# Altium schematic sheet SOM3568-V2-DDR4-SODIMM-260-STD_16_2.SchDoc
size 594 x 420 mm
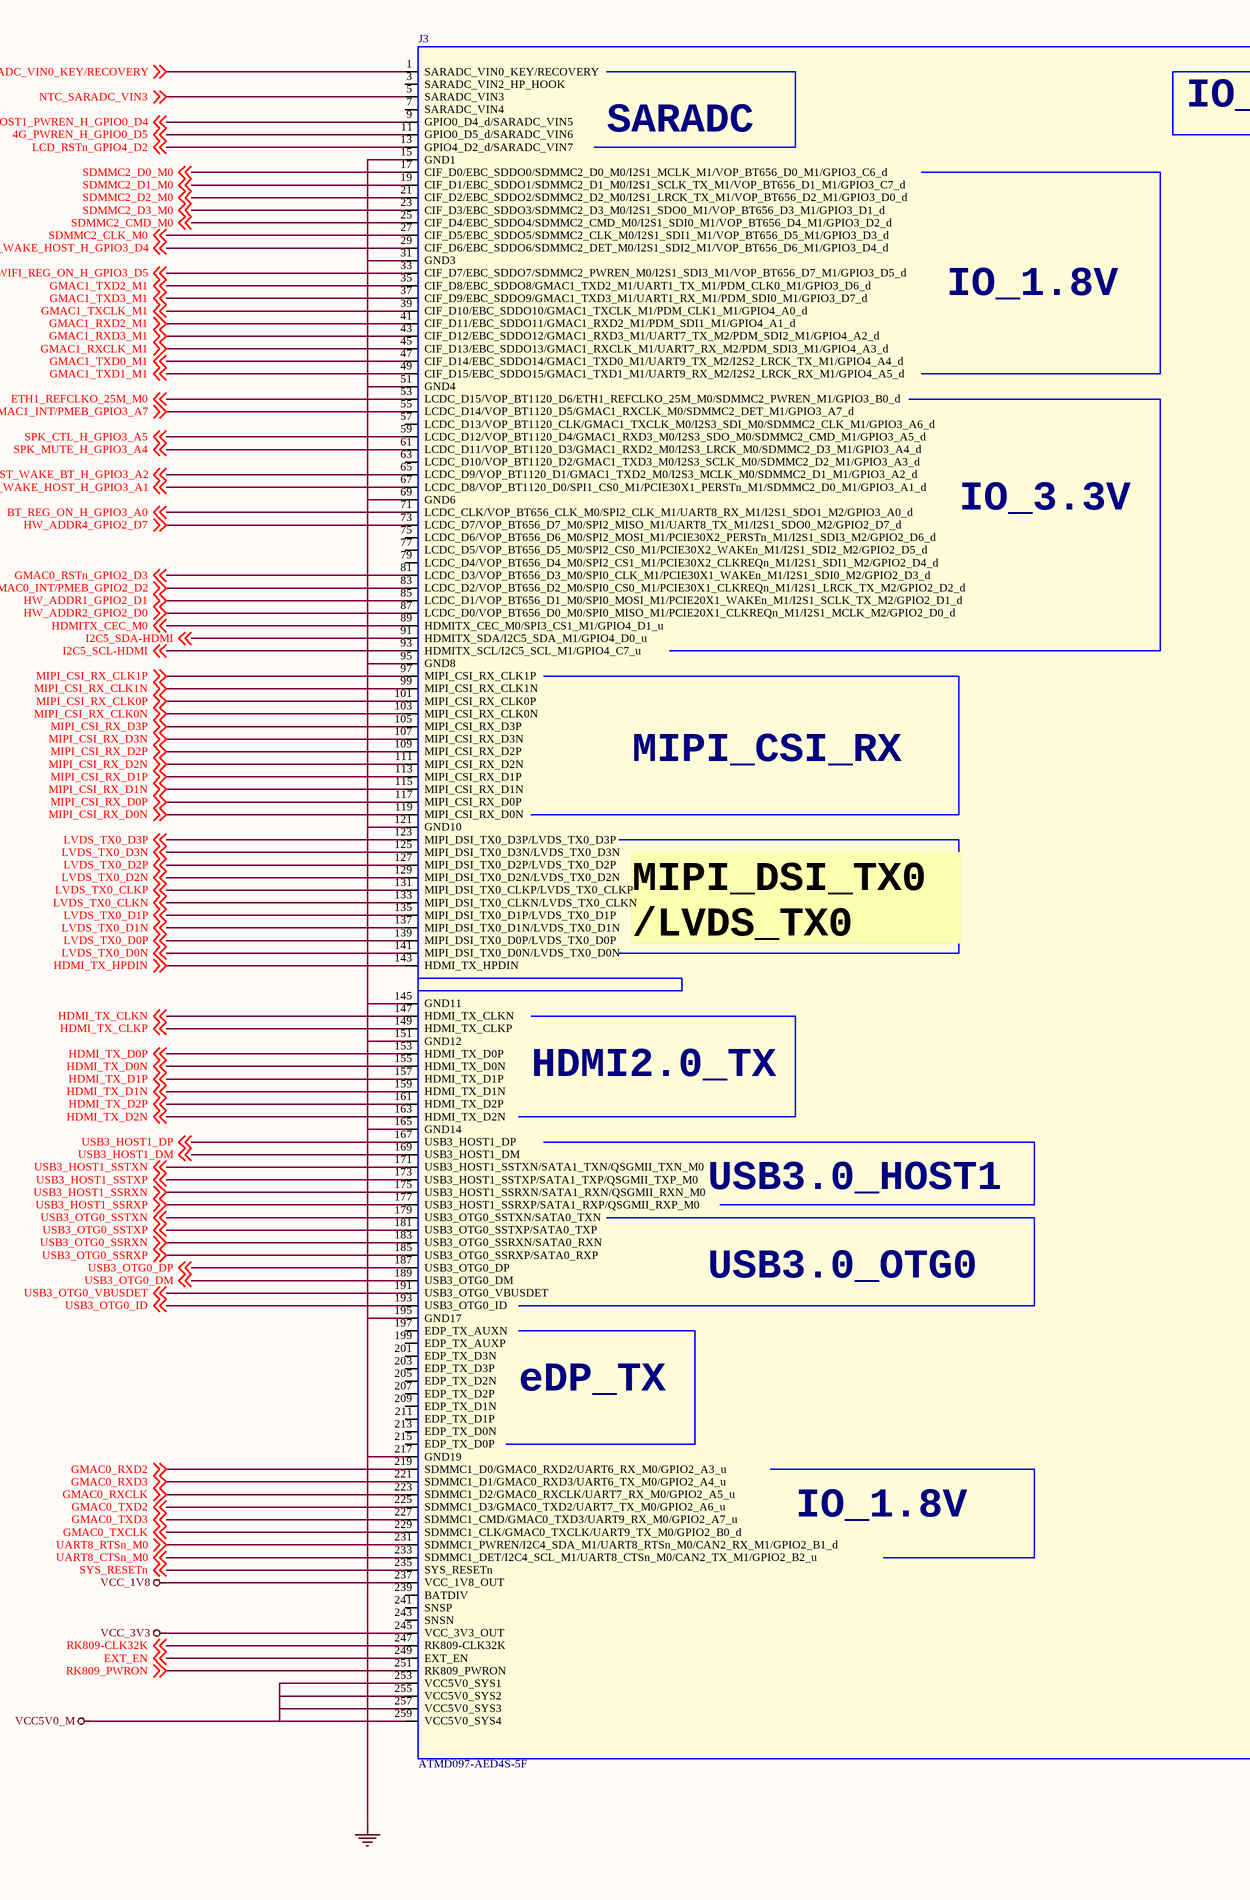
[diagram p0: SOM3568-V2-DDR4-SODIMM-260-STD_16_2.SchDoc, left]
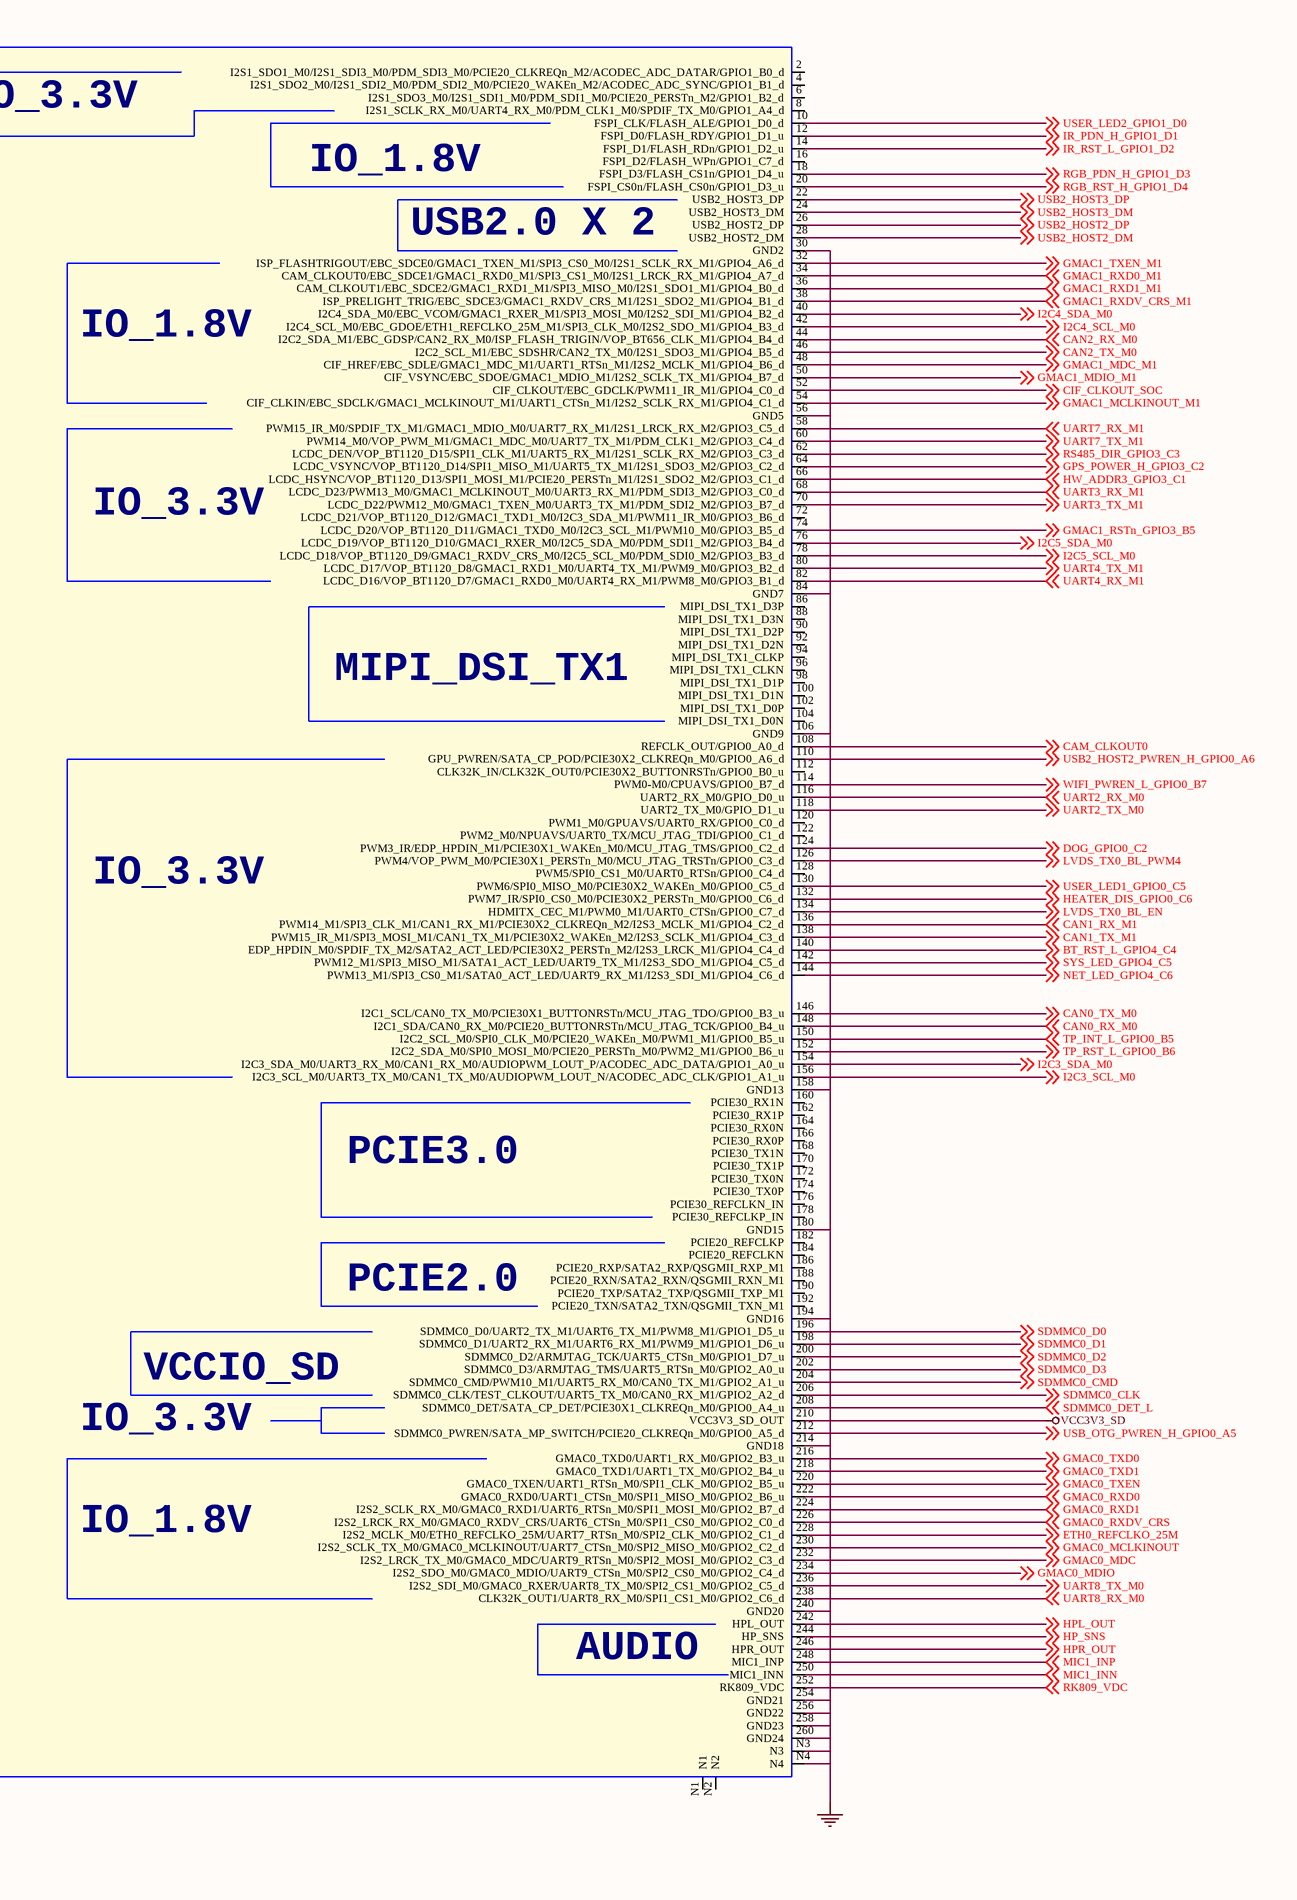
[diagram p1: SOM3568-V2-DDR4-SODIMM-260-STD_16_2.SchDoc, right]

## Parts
J3  ATMD097-AED4S-5F  [DDR4-SODIMM-260P-STD]

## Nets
GND: J3.15(GND1) J3.30(GND2) J3.31(GND3) J3.51(GND4) J3.56(GND5) J3.69(GND6) J3.84(GND7) J3.95(GND8) J3.106(GND9) J3.121(GND10) J3.145(GND11) J3.151(GND12) J3.158(GND13) J3.165(GND14) J3.180(GND15) J3.194(GND16) J3.195(GND17) J3.214(GND18) J3.217(GND19) J3.240(GND20) J3.254(GND21) J3.256(GND22) J3.258(GND23) J3.260(GND24) J3.N3 J3.N4
VCC3V3_SD: J3.210(VCC3V3_SD_OUT)
VCC5V0_M: J3.253(VCC5V0_SYS1) J3.255(VCC5V0_SYS2) J3.257(VCC5V0_SYS3) J3.259(VCC5V0_SYS4)
VCC_1V8: J3.237(VCC_1V8_OUT)
VCC_3V3: J3.245(VCC_3V3_OUT)
4G_PWREN_H_GPIO0_D5: J3.11(GPIO0_D5_d/SARADC_VIN6) ; off-sheet 4G_PWREN_H_GPIO0_D5
BT_REG_ON_H_GPIO3_A0: J3.71(LCDC_CLK/VOP_BT656_CLK_M0/SPI2_CLK_M1/UART8_RX_M1/I2S1_SDO1_M2/GPIO3_A0_d) ; off-sheet BT_REG_ON_H_GPIO3_A0
BT_RST_L_GPIO4_C4: J3.140(EDP_HPDIN_M0/SPDIF_TX_M2/SATA2_ACT_LED/PCIE30X2_PERSTn_M2/I2S3_LRCK_M1/GPIO4_C4_d) ; off-sheet BT_RST_L_GPIO4_C4
BT_WAKE_HOST_H_GPIO3_A1: J3.67(LCDC_D8/VOP_BT1120_D0/SPI1_CS0_M1/PCIE30X1_PERSTn_M1/SDMMC2_D0_M1/GPIO3_A1_d) ; off-sheet BT_WAKE_HOST_H_GPIO3_A1
CAM_CLKOUT0: J3.108(REFCLK_OUT/GPIO0_A0_d) ; off-sheet CAM_CLKOUT0
CAN0_RX_M0: J3.148(I2C1_SDA/CAN0_RX_M0/PCIE20_BUTTONRSTn/MCU_JTAG_TCK/GPIO0_B4_u) ; off-sheet CAN0_RX_M0
CAN0_TX_M0: J3.146(I2C1_SCL/CAN0_TX_M0/PCIE30X1_BUTTONRSTn/MCU_JTAG_TDO/GPIO0_B3_u) ; off-sheet CAN0_TX_M0
CAN1_RX_M1: J3.136(PWM14_M1/SPI3_CLK_M1/CAN1_RX_M1/PCIE30X2_CLKREQn_M2/I2S3_MCLK_M1/GPIO4_C2_d) ; off-sheet CAN1_RX_M1
CAN1_TX_M1: J3.138(PWM15_IR_M1/SPI3_MOSI_M1/CAN1_TX_M1/PCIE30X2_WAKEn_M2/I2S3_SCLK_M1/GPIO4_C3_d) ; off-sheet CAN1_TX_M1
CAN2_RX_M0: J3.44(I2C2_SDA_M1/EBC_GDSP/CAN2_RX_M0/ISP_FLASH_TRIGIN/VOP_BT656_CLK_M1/GPIO4_B4_d) ; off-sheet CAN2_RX_M0
CAN2_TX_M0: J3.46(I2C2_SCL_M1/EBC_SDSHR/CAN2_TX_M0/I2S1_SDO3_M1/GPIO4_B5_d) ; off-sheet CAN2_TX_M0
CIF_CLKOUT_SOC: J3.52(CIF_CLKOUT/EBC_GDCLK/PWM11_IR_M1/GPIO4_C0_d) ; off-sheet CIF_CLKOUT_SOC
DOG_GPIO0_C2: J3.124(PWM3_IR/EDP_HPDIN_M1/PCIE30X1_WAKEn_M0/MCU_JTAG_TMS/GPIO0_C2_d) ; off-sheet DOG_GPIO0_C2
ETH0_REFCLKO_25M: J3.228(I2S2_MCLK_M0/ETH0_REFCLKO_25M/UART7_RTSn_M0/SPI2_CLK_M0/GPIO2_C1_d) ; off-sheet ETH0_REFCLKO_25M
ETH1_REFCLKO_25M_M0: J3.53(LCDC_D15/VOP_BT1120_D6/ETH1_REFCLKO_25M_M0/SDMMC2_PWREN_M1/GPIO3_B0_d) ; off-sheet ETH1_REFCLKO_25M_M0
EXT_EN: J3.249(EXT_EN) ; off-sheet EXT_EN
GMAC0_INT/PMEB_GPIO2_D2: J3.83(LCDC_D2/VOP_BT656_D2_M0/SPI0_CS0_M1/PCIE30X1_CLKREQn_M1/I2S1_LRCK_TX_M2/GPIO2_D2_d) ; off-sheet GMAC0_INT/PMEB_GPIO2_D2
GMAC0_MCLKINOUT: J3.230(I2S2_SCLK_TX_M0/GMAC0_MCLKINOUT/UART7_CTSn_M0/SPI2_MISO_M0/GPIO2_C2_d) ; off-sheet GMAC0_MCLKINOUT
GMAC0_MDC: J3.232(I2S2_LRCK_TX_M0/GMAC0_MDC/UART9_RTSn_M0/SPI2_MOSI_M0/GPIO2_C3_d) ; off-sheet GMAC0_MDC
GMAC0_MDIO: J3.234(I2S2_SDO_M0/GMAC0_MDIO/UART9_CTSn_M0/SPI2_CS0_M0/GPIO2_C4_d) ; off-sheet GMAC0_MDIO
GMAC0_RSTn_GPIO2_D3: J3.81(LCDC_D3/VOP_BT656_D3_M0/SPI0_CLK_M1/PCIE30X1_WAKEn_M1/I2S1_SDI0_M2/GPIO2_D3_d) ; off-sheet GMAC0_RSTn_GPIO2_D3
GMAC0_RXCLK: J3.223(SDMMC1_D2/GMAC0_RXCLK/UART7_RX_M0/GPIO2_A5_u) ; off-sheet GMAC0_RXCLK
GMAC0_RXD0: J3.222(GMAC0_RXD0/UART1_CTSn_M0/SPI1_MISO_M0/GPIO2_B6_u) ; off-sheet GMAC0_RXD0
GMAC0_RXD1: J3.224(I2S2_SCLK_RX_M0/GMAC0_RXD1/UART6_RTSn_M0/SPI1_MOSI_M0/GPIO2_B7_d) ; off-sheet GMAC0_RXD1
GMAC0_RXD2: J3.219(SDMMC1_D0/GMAC0_RXD2/UART6_RX_M0/GPIO2_A3_u) ; off-sheet GMAC0_RXD2
GMAC0_RXD3: J3.221(SDMMC1_D1/GMAC0_RXD3/UART6_TX_M0/GPIO2_A4_u) ; off-sheet GMAC0_RXD3
GMAC0_RXDV_CRS: J3.226(I2S2_LRCK_RX_M0/GMAC0_RXDV_CRS/UART6_CTSn_M0/SPI1_CS0_M0/GPIO2_C0_d) ; off-sheet GMAC0_RXDV_CRS
GMAC0_TXCLK: J3.229(SDMMC1_CLK/GMAC0_TXCLK/UART9_TX_M0/GPIO2_B0_d) ; off-sheet GMAC0_TXCLK
GMAC0_TXD0: J3.216(GMAC0_TXD0/UART1_RX_M0/GPIO2_B3_u) ; off-sheet GMAC0_TXD0
GMAC0_TXD1: J3.218(GMAC0_TXD1/UART1_TX_M0/GPIO2_B4_u) ; off-sheet GMAC0_TXD1
GMAC0_TXD2: J3.225(SDMMC1_D3/GMAC0_TXD2/UART7_TX_M0/GPIO2_A6_u) ; off-sheet GMAC0_TXD2
GMAC0_TXD3: J3.227(SDMMC1_CMD/GMAC0_TXD3/UART9_RX_M0/GPIO2_A7_u) ; off-sheet GMAC0_TXD3
GMAC0_TXEN: J3.220(GMAC0_TXEN/UART1_RTSn_M0/SPI1_CLK_M0/GPIO2_B5_u) ; off-sheet GMAC0_TXEN
GMAC1_INT/PMEB_GPIO3_A7: J3.55(LCDC_D14/VOP_BT1120_D5/GMAC1_RXCLK_M0/SDMMC2_DET_M1/GPIO3_A7_d) ; off-sheet GMAC1_INT/PMEB_GPIO3_A7
GMAC1_MCLKINOUT_M1: J3.54(CIF_CLKIN/EBC_SDCLK/GMAC1_MCLKINOUT_M1/UART1_CTSn_M1/I2S2_SCLK_RX_M1/GPIO4_C1_d) ; off-sheet GMAC1_MCLKINOUT_M1
GMAC1_MDC_M1: J3.48(CIF_HREF/EBC_SDLE/GMAC1_MDC_M1/UART1_RTSn_M1/I2S2_MCLK_M1/GPIO4_B6_d) ; off-sheet GMAC1_MDC_M1
GMAC1_MDIO_M1: J3.50(CIF_VSYNC/EBC_SDOE/GMAC1_MDIO_M1/I2S2_SCLK_TX_M1/GPIO4_B7_d) ; off-sheet GMAC1_MDIO_M1
GMAC1_RSTn_GPIO3_B5: J3.74(LCDC_D20/VOP_BT1120_D11/GMAC1_TXD0_M0/I2C3_SCL_M1/PWM10_M0/GPIO3_B5_d) ; off-sheet GMAC1_RSTn_GPIO3_B5
GMAC1_RXCLK_M1: J3.45(CIF_D13/EBC_SDDO13/GMAC1_RXCLK_M1/UART7_RX_M2/PDM_SDI3_M1/GPIO4_A3_d) ; off-sheet GMAC1_RXCLK_M1
GMAC1_RXD0_M1: J3.34(CAM_CLKOUT0/EBC_SDCE1/GMAC1_RXD0_M1/SPI3_CS1_M0/I2S1_LRCK_RX_M1/GPIO4_A7_d) ; off-sheet GMAC1_RXD0_M1
GMAC1_RXD1_M1: J3.36(CAM_CLKOUT1/EBC_SDCE2/GMAC1_RXD1_M1/SPI3_MISO_M0/I2S1_SDO1_M1/GPIO4_B0_d) ; off-sheet GMAC1_RXD1_M1
GMAC1_RXD2_M1: J3.41(CIF_D11/EBC_SDDO11/GMAC1_RXD2_M1/PDM_SDI1_M1/GPIO4_A1_d) ; off-sheet GMAC1_RXD2_M1
GMAC1_RXD3_M1: J3.43(CIF_D12/EBC_SDDO12/GMAC1_RXD3_M1/UART7_TX_M2/PDM_SDI2_M1/GPIO4_A2_d) ; off-sheet GMAC1_RXD3_M1
GMAC1_RXDV_CRS_M1: J3.38(ISP_PRELIGHT_TRIG/EBC_SDCE3/GMAC1_RXDV_CRS_M1/I2S1_SDO2_M1/GPIO4_B1_d) ; off-sheet GMAC1_RXDV_CRS_M1
GMAC1_TXCLK_M1: J3.39(CIF_D10/EBC_SDDO10/GMAC1_TXCLK_M1/PDM_CLK1_M1/GPIO4_A0_d) ; off-sheet GMAC1_TXCLK_M1
GMAC1_TXD0_M1: J3.47(CIF_D14/EBC_SDDO14/GMAC1_TXD0_M1/UART9_TX_M2/I2S2_LRCK_TX_M1/GPIO4_A4_d) ; off-sheet GMAC1_TXD0_M1
GMAC1_TXD1_M1: J3.49(CIF_D15/EBC_SDDO15/GMAC1_TXD1_M1/UART9_RX_M2/I2S2_LRCK_RX_M1/GPIO4_A5_d) ; off-sheet GMAC1_TXD1_M1
GMAC1_TXD2_M1: J3.35(CIF_D8/EBC_SDDO8/GMAC1_TXD2_M1/UART1_TX_M1/PDM_CLK0_M1/GPIO3_D6_d) ; off-sheet GMAC1_TXD2_M1
GMAC1_TXD3_M1: J3.37(CIF_D9/EBC_SDDO9/GMAC1_TXD3_M1/UART1_RX_M1/PDM_SDI0_M1/GPIO3_D7_d) ; off-sheet GMAC1_TXD3_M1
GMAC1_TXEN_M1: J3.32(ISP_FLASHTRIGOUT/EBC_SDCE0/GMAC1_TXEN_M1/SPI3_CS0_M0/I2S1_SCLK_RX_M1/GPIO4_A6_d) ; off-sheet GMAC1_TXEN_M1
GPS_POWER_H_GPIO3_C2: J3.64(LCDC_VSYNC/VOP_BT1120_D14/SPI1_MISO_M1/UART5_TX_M1/I2S1_SDO3_M2/GPIO3_C2_d) ; off-sheet GPS_POWER_H_GPIO3_C2
HDMI_TX_CLKN: J3.147(HDMI_TX_CLKN) ; off-sheet HDMI_TX_CLKN
HDMI_TX_CLKP: J3.149(HDMI_TX_CLKP) ; off-sheet HDMI_TX_CLKP
HDMI_TX_D0N: J3.155(HDMI_TX_D0N) ; off-sheet HDMI_TX_D0N
HDMI_TX_D0P: J3.153(HDMI_TX_D0P) ; off-sheet HDMI_TX_D0P
HDMI_TX_D1N: J3.159(HDMI_TX_D1N) ; off-sheet HDMI_TX_D1N
HDMI_TX_D1P: J3.157(HDMI_TX_D1P) ; off-sheet HDMI_TX_D1P
HDMI_TX_D2N: J3.163(HDMI_TX_D2N) ; off-sheet HDMI_TX_D2N
HDMI_TX_D2P: J3.161(HDMI_TX_D2P) ; off-sheet HDMI_TX_D2P
HDMI_TX_HPDIN: J3.143(HDMI_TX_HPDIN) ; off-sheet HDMI_TX_HPDIN
HDMITX_CEC_M0: J3.89(HDMITX_CEC_M0/SPI3_CS1_M1/GPIO4_D1_u) ; off-sheet HDMITX_CEC_M0
HEATER_DIS_GPIO0_C6: J3.132(PWM7_IR/SPI0_CS0_M0/PCIE30X2_PERSTn_M0/GPIO0_C6_d) ; off-sheet HEATER_DIS_GPIO0_C6
HOST_WAKE_BT_H_GPIO3_A2: J3.65(LCDC_D9/VOP_BT1120_D1/GMAC1_TXD2_M0/I2S3_MCLK_M0/SDMMC2_D1_M1/GPIO3_A2_d) ; off-sheet HOST_WAKE_BT_H_GPIO3_A2
HP_SNS: J3.244(HP_SNS) ; off-sheet HP_SNS
HPL_OUT: J3.242(HPL_OUT) ; off-sheet HPL_OUT
HPR_OUT: J3.246(HPR_OUT) ; off-sheet HPR_OUT
HW_ADDR1_GPIO2_D1: J3.85(LCDC_D1/VOP_BT656_D1_M0/SPI0_MOSI_M1/PCIE20X1_WAKEn_M1/I2S1_SCLK_TX_M2/GPIO2_D1_d) ; off-sheet HW_ADDR1_GPIO2_D1
HW_ADDR2_GPIO2_D0: J3.87(LCDC_D0/VOP_BT656_D0_M0/SPI0_MISO_M1/PCIE20X1_CLKREQn_M1/I2S1_MCLK_M2/GPIO2_D0_d) ; off-sheet HW_ADDR2_GPIO2_D0
HW_ADDR3_GPIO3_C1: J3.66(LCDC_HSYNC/VOP_BT1120_D13/SPI1_MOSI_M1/PCIE20_PERSTn_M1/I2S1_SDO2_M2/GPIO3_C1_d) ; off-sheet HW_ADDR3_GPIO3_C1
HW_ADDR4_GPIO2_D7: J3.73(LCDC_D7/VOP_BT656_D7_M0/SPI2_MISO_M1/UART8_TX_M1/I2S1_SDO0_M2/GPIO2_D7_d) ; off-sheet HW_ADDR4_GPIO2_D7
I2C3_SCL_M0: J3.156(I2C3_SCL_M0/UART3_TX_M0/CAN1_TX_M0/AUDIOPWM_LOUT_N/ACODEC_ADC_CLK/GPIO1_A1_u) ; off-sheet I2C3_SCL_M0
I2C3_SDA_M0: J3.154(I2C3_SDA_M0/UART3_RX_M0/CAN1_RX_M0/AUDIOPWM_LOUT_P/ACODEC_ADC_DATA/GPIO1_A0_u) ; off-sheet I2C3_SDA_M0
I2C4_SCL_M0: J3.42(I2C4_SCL_M0/EBC_GDOE/ETH1_REFCLKO_25M_M1/SPI3_CLK_M0/I2S2_SDO_M1/GPIO4_B3_d) ; off-sheet I2C4_SCL_M0
I2C4_SDA_M0: J3.40(I2C4_SDA_M0/EBC_VCOM/GMAC1_RXER_M1/SPI3_MOSI_M0/I2S2_SDI_M1/GPIO4_B2_d) ; off-sheet I2C4_SDA_M0
I2C5_SCL-HDMI: J3.93(HDMITX_SCL/I2C5_SCL_M1/GPIO4_C7_u) ; off-sheet I2C5_SCL-HDMI
I2C5_SCL_M0: J3.78(LCDC_D18/VOP_BT1120_D9/GMAC1_RXDV_CRS_M0/I2C5_SCL_M0/PDM_SDI0_M2/GPIO3_B3_d) ; off-sheet I2C5_SCL_M0
I2C5_SDA-HDMI: J3.91(HDMITX_SDA/I2C5_SDA_M1/GPIO4_D0_u) ; off-sheet I2C5_SDA-HDMI
I2C5_SDA_M0: J3.76(LCDC_D19/VOP_BT1120_D10/GMAC1_RXER_M0/I2C5_SDA_M0/PDM_SDI1_M2/GPIO3_B4_d) ; off-sheet I2C5_SDA_M0
IR_PDN_H_GPIO1_D1: J3.12(FSPI_D0/FLASH_RDY/GPIO1_D1_u) ; off-sheet IR_PDN_H_GPIO1_D1
IR_RST_L_GPIO1_D2: J3.14(FSPI_D1/FLASH_RDn/GPIO1_D2_u) ; off-sheet IR_RST_L_GPIO1_D2
LCD_RSTn_GPIO4_D2: J3.13(GPIO4_D2_d/SARADC_VIN7) ; off-sheet LCD_RSTn_GPIO4_D2
LVDS_TX0_BL_EN: J3.134(HDMITX_CEC_M1/PWM0_M1/UART0_CTSn/GPIO0_C7_d) ; off-sheet LVDS_TX0_BL_EN
LVDS_TX0_BL_PWM4: J3.126(PWM4/VOP_PWM_M0/PCIE30X1_PERSTn_M0/MCU_JTAG_TRSTn/GPIO0_C3_d) ; off-sheet LVDS_TX0_BL_PWM4
LVDS_TX0_CLKN: J3.133(MIPI_DSI_TX0_CLKN/LVDS_TX0_CLKN) ; off-sheet LVDS_TX0_CLKN
LVDS_TX0_CLKP: J3.131(MIPI_DSI_TX0_CLKP/LVDS_TX0_CLKP) ; off-sheet LVDS_TX0_CLKP
LVDS_TX0_D0N: J3.141(MIPI_DSI_TX0_D0N/LVDS_TX0_D0N) ; off-sheet LVDS_TX0_D0N
LVDS_TX0_D0P: J3.139(MIPI_DSI_TX0_D0P/LVDS_TX0_D0P) ; off-sheet LVDS_TX0_D0P
LVDS_TX0_D1N: J3.137(MIPI_DSI_TX0_D1N/LVDS_TX0_D1N) ; off-sheet LVDS_TX0_D1N
LVDS_TX0_D1P: J3.135(MIPI_DSI_TX0_D1P/LVDS_TX0_D1P) ; off-sheet LVDS_TX0_D1P
LVDS_TX0_D2N: J3.129(MIPI_DSI_TX0_D2N/LVDS_TX0_D2N) ; off-sheet LVDS_TX0_D2N
LVDS_TX0_D2P: J3.127(MIPI_DSI_TX0_D2P/LVDS_TX0_D2P) ; off-sheet LVDS_TX0_D2P
LVDS_TX0_D3N: J3.125(MIPI_DSI_TX0_D3N/LVDS_TX0_D3N) ; off-sheet LVDS_TX0_D3N
LVDS_TX0_D3P: J3.123(MIPI_DSI_TX0_D3P/LVDS_TX0_D3P) ; off-sheet LVDS_TX0_D3P
MIC1_INN: J3.250(MIC1_INN) ; off-sheet MIC1_INN
MIC1_INP: J3.248(MIC1_INP) ; off-sheet MIC1_INP
MIPI_CSI_RX_CLK0N: J3.103(MIPI_CSI_RX_CLK0N) ; off-sheet MIPI_CSI_RX_CLK0N
MIPI_CSI_RX_CLK0P: J3.101(MIPI_CSI_RX_CLK0P) ; off-sheet MIPI_CSI_RX_CLK0P
MIPI_CSI_RX_CLK1N: J3.99(MIPI_CSI_RX_CLK1N) ; off-sheet MIPI_CSI_RX_CLK1N
MIPI_CSI_RX_CLK1P: J3.97(MIPI_CSI_RX_CLK1P) ; off-sheet MIPI_CSI_RX_CLK1P
MIPI_CSI_RX_D0N: J3.119(MIPI_CSI_RX_D0N) ; off-sheet MIPI_CSI_RX_D0N
MIPI_CSI_RX_D0P: J3.117(MIPI_CSI_RX_D0P) ; off-sheet MIPI_CSI_RX_D0P
MIPI_CSI_RX_D1N: J3.115(MIPI_CSI_RX_D1N) ; off-sheet MIPI_CSI_RX_D1N
MIPI_CSI_RX_D1P: J3.113(MIPI_CSI_RX_D1P) ; off-sheet MIPI_CSI_RX_D1P
MIPI_CSI_RX_D2N: J3.111(MIPI_CSI_RX_D2N) ; off-sheet MIPI_CSI_RX_D2N
MIPI_CSI_RX_D2P: J3.109(MIPI_CSI_RX_D2P) ; off-sheet MIPI_CSI_RX_D2P
MIPI_CSI_RX_D3N: J3.107(MIPI_CSI_RX_D3N) ; off-sheet MIPI_CSI_RX_D3N
MIPI_CSI_RX_D3P: J3.105(MIPI_CSI_RX_D3P) ; off-sheet MIPI_CSI_RX_D3P
NET_LED_GPIO4_C6: J3.144(PWM13_M1/SPI3_CS0_M1/SATA0_ACT_LED/UART9_RX_M1/I2S3_SDI_M1/GPIO4_C6_d) ; off-sheet NET_LED_GPIO4_C6
NTC_SARADC_VIN3: J3.5(SARADC_VIN3) ; off-sheet NTC_SARADC_VIN3
RGB_PDN_H_GPIO1_D3: J3.18(FSPI_D3/FLASH_CS1n/GPIO1_D4_u) ; off-sheet RGB_PDN_H_GPIO1_D3
RGB_RST_H_GPIO1_D4: J3.20(FSPI_CS0n/FLASH_CS0n/GPIO1_D3_u) ; off-sheet RGB_RST_H_GPIO1_D4
RK809-CLK32K: J3.247(RK809-CLK32K) ; off-sheet RK809-CLK32K
RK809_PWRON: J3.251(RK809_PWRON) ; off-sheet RK809_PWRON
RK809_VDC: J3.252(RK809_VDC) ; off-sheet RK809_VDC
RS485_DIR_GPIO3_C3: J3.62(LCDC_DEN/VOP_BT1120_D15/SPI1_CLK_M1/UART5_RX_M1/I2S1_SCLK_RX_M2/GPIO3_C3_d) ; off-sheet RS485_DIR_GPIO3_C3
SARADC_VIN0_KEY/RECOVERY: J3.1(SARADC_VIN0_KEY/RECOVERY) ; off-sheet SARADC_VIN0_KEY/RECOVERY
SDMMC0_CLK: J3.206(SDMMC0_CLK/TEST_CLKOUT/UART5_TX_M0/CAN0_RX_M1/GPIO2_A2_d) ; off-sheet SDMMC0_CLK
SDMMC0_CMD: J3.204(SDMMC0_CMD/PWM10_M1/UART5_RX_M0/CAN0_TX_M1/GPIO2_A1_u) ; off-sheet SDMMC0_CMD
SDMMC0_D0: J3.196(SDMMC0_D0/UART2_TX_M1/UART6_TX_M1/PWM8_M1/GPIO1_D5_u) ; off-sheet SDMMC0_D0
SDMMC0_D1: J3.198(SDMMC0_D1/UART2_RX_M1/UART6_RX_M1/PWM9_M1/GPIO1_D6_u) ; off-sheet SDMMC0_D1
SDMMC0_D2: J3.200(SDMMC0_D2/ARMJTAG_TCK/UART5_CTSn_M0/GPIO1_D7_u) ; off-sheet SDMMC0_D2
SDMMC0_D3: J3.202(SDMMC0_D3/ARMJTAG_TMS/UART5_RTSn_M0/GPIO2_A0_u) ; off-sheet SDMMC0_D3
SDMMC0_DET_L: J3.208(SDMMC0_DET/SATA_CP_DET/PCIE30X1_CLKREQn_M0/GPIO0_A4_u) ; off-sheet SDMMC0_DET_L
SDMMC2_CLK_M0: J3.27(CIF_D5/EBC_SDDO5/SDMMC2_CLK_M0/I2S1_SDI1_M1/VOP_BT656_D5_M1/GPIO3_D3_d) ; off-sheet SDMMC2_CLK_M0
SDMMC2_CMD_M0: J3.25(CIF_D4/EBC_SDDO4/SDMMC2_CMD_M0/I2S1_SDI0_M1/VOP_BT656_D4_M1/GPIO3_D2_d) ; off-sheet SDMMC2_CMD_M0
SDMMC2_D0_M0: J3.17(CIF_D0/EBC_SDDO0/SDMMC2_D0_M0/I2S1_MCLK_M1/VOP_BT656_D0_M1/GPIO3_C6_d) ; off-sheet SDMMC2_D0_M0
SDMMC2_D1_M0: J3.19(CIF_D1/EBC_SDDO1/SDMMC2_D1_M0/I2S1_SCLK_TX_M1/VOP_BT656_D1_M1/GPIO3_C7_d) ; off-sheet SDMMC2_D1_M0
SDMMC2_D2_M0: J3.21(CIF_D2/EBC_SDDO2/SDMMC2_D2_M0/I2S1_LRCK_TX_M1/VOP_BT656_D2_M1/GPIO3_D0_d) ; off-sheet SDMMC2_D2_M0
SDMMC2_D3_M0: J3.23(CIF_D3/EBC_SDDO3/SDMMC2_D3_M0/I2S1_SDO0_M1/VOP_BT656_D3_M1/GPIO3_D1_d) ; off-sheet SDMMC2_D3_M0
SPK_CTL_H_GPIO3_A5: J3.59(LCDC_D12/VOP_BT1120_D4/GMAC1_RXD3_M0/I2S3_SDO_M0/SDMMC2_CMD_M1/GPIO3_A5_d) ; off-sheet SPK_CTL_H_GPIO3_A5
SPK_MUTE_H_GPIO3_A4: J3.61(LCDC_D11/VOP_BT1120_D3/GMAC1_RXD2_M0/I2S3_LRCK_M0/SDMMC2_D3_M1/GPIO3_A4_d) ; off-sheet SPK_MUTE_H_GPIO3_A4
SYS_LED_GPIO4_C5: J3.142(PWM12_M1/SPI3_MISO_M1/SATA1_ACT_LED/UART9_TX_M1/I2S3_SDO_M1/GPIO4_C5_d) ; off-sheet SYS_LED_GPIO4_C5
SYS_RESETn: J3.235(SYS_RESETn) ; off-sheet SYS_RESETn
TP_INT_L_GPIO0_B5: J3.150(I2C2_SCL_M0/SPI0_CLK_M0/PCIE20_WAKEn_M0/PWM1_M1/GPIO0_B5_u) ; off-sheet TP_INT_L_GPIO0_B5
TP_RST_L_GPIO0_B6: J3.152(I2C2_SDA_M0/SPI0_MOSI_M0/PCIE20_PERSTn_M0/PWM2_M1/GPIO0_B6_u) ; off-sheet TP_RST_L_GPIO0_B6
UART2_RX_M0: J3.116(UART2_RX_M0/GPIO_D0_u) ; off-sheet UART2_RX_M0
UART2_TX_M0: J3.118(UART2_TX_M0/GPIO_D1_u) ; off-sheet UART2_TX_M0
UART3_RX_M1: J3.68(LCDC_D23/PWM13_M0/GMAC1_MCLKINOUT_M0/UART3_RX_M1/PDM_SDI3_M2/GPIO3_C0_d) ; off-sheet UART3_RX_M1
UART3_TX_M1: J3.70(LCDC_D22/PWM12_M0/GMAC1_TXEN_M0/UART3_TX_M1/PDM_SDI2_M2/GPIO3_B7_d) ; off-sheet UART3_TX_M1
UART4_RX_M1: J3.82(LCDC_D16/VOP_BT1120_D7/GMAC1_RXD0_M0/UART4_RX_M1/PWM8_M0/GPIO3_B1_d) ; off-sheet UART4_RX_M1
UART4_TX_M1: J3.80(LCDC_D17/VOP_BT1120_D8/GMAC1_RXD1_M0/UART4_TX_M1/PWM9_M0/GPIO3_B2_d) ; off-sheet UART4_TX_M1
UART7_RX_M1: J3.58(PWM15_IR_M0/SPDIF_TX_M1/GMAC1_MDIO_M0/UART7_RX_M1/I2S1_LRCK_RX_M2/GPIO3_C5_d) ; off-sheet UART7_RX_M1
UART7_TX_M1: J3.60(PWM14_M0/VOP_PWM_M1/GMAC1_MDC_M0/UART7_TX_M1/PDM_CLK1_M2/GPIO3_C4_d) ; off-sheet UART7_TX_M1
UART8_CTSn_M0: J3.233(SDMMC1_DET/I2C4_SCL_M1/UART8_CTSn_M0/CAN2_TX_M1/GPIO2_B2_u) ; off-sheet UART8_CTSn_M0
UART8_RTSn_M0: J3.231(SDMMC1_PWREN/I2C4_SDA_M1/UART8_RTSn_M0/CAN2_RX_M1/GPIO2_B1_d) ; off-sheet UART8_RTSn_M0
UART8_RX_M0: J3.238(CLK32K_OUT1/UART8_RX_M0/SPI1_CS1_M0/GPIO2_C6_d) ; off-sheet UART8_RX_M0
UART8_TX_M0: J3.236(I2S2_SDI_M0/GMAC0_RXER/UART8_TX_M0/SPI2_CS1_M0/GPIO2_C5_d) ; off-sheet UART8_TX_M0
USB2_HOST2_DM: J3.28(USB2_HOST2_DM) ; off-sheet USB2_HOST2_DM
USB2_HOST2_DP: J3.26(USB2_HOST2_DP) ; off-sheet USB2_HOST2_DP
USB2_HOST2_PWREN_H_GPIO0_A6: J3.110(GPU_PWREN/SATA_CP_POD/PCIE30X2_CLKREQn_M0/GPIO0_A6_d) ; off-sheet USB2_HOST2_PWREN_H_GPIO0_A6
USB2_HOST3_DM: J3.24(USB2_HOST3_DM) ; off-sheet USB2_HOST3_DM
USB2_HOST3_DP: J3.22(USB2_HOST3_DP) ; off-sheet USB2_HOST3_DP
USB3_HOST1_DM: J3.169(USB3_HOST1_DM) ; off-sheet USB3_HOST1_DM
USB3_HOST1_DP: J3.167(USB3_HOST1_DP) ; off-sheet USB3_HOST1_DP
USB3_HOST1_PWREN_H_GPIO0_D4: J3.9(GPIO0_D4_d/SARADC_VIN5) ; off-sheet USB3_HOST1_PWREN_H_GPIO0_D4
USB3_HOST1_SSRXN: J3.175(USB3_HOST1_SSRXN/SATA1_RXN/QSGMII_RXN_M0) ; off-sheet USB3_HOST1_SSRXN
USB3_HOST1_SSRXP: J3.177(USB3_HOST1_SSRXP/SATA1_RXP/QSGMII_RXP_M0) ; off-sheet USB3_HOST1_SSRXP
USB3_HOST1_SSTXN: J3.171(USB3_HOST1_SSTXN/SATA1_TXN/QSGMII_TXN_M0) ; off-sheet USB3_HOST1_SSTXN
USB3_HOST1_SSTXP: J3.173(USB3_HOST1_SSTXP/SATA1_TXP/QSGMII_TXP_M0) ; off-sheet USB3_HOST1_SSTXP
USB3_OTG0_DM: J3.189(USB3_OTG0_DM) ; off-sheet USB3_OTG0_DM
USB3_OTG0_DP: J3.187(USB3_OTG0_DP) ; off-sheet USB3_OTG0_DP
USB3_OTG0_ID: J3.193(USB3_OTG0_ID) ; off-sheet USB3_OTG0_ID
USB3_OTG0_SSRXN: J3.183(USB3_OTG0_SSRXN/SATA0_RXN) ; off-sheet USB3_OTG0_SSRXN
USB3_OTG0_SSRXP: J3.185(USB3_OTG0_SSRXP/SATA0_RXP) ; off-sheet USB3_OTG0_SSRXP
USB3_OTG0_SSTXN: J3.179(USB3_OTG0_SSTXN/SATA0_TXN) ; off-sheet USB3_OTG0_SSTXN
USB3_OTG0_SSTXP: J3.181(USB3_OTG0_SSTXP/SATA0_TXP) ; off-sheet USB3_OTG0_SSTXP
USB3_OTG0_VBUSDET: J3.191(USB3_OTG0_VBUSDET) ; off-sheet USB3_OTG0_VBUSDET
USB_OTG_PWREN_H_GPIO0_A5: J3.212(SDMMC0_PWREN/SATA_MP_SWITCH/PCIE20_CLKREQn_M0/GPIO0_A5_d) ; off-sheet USB_OTG_PWREN_H_GPIO0_A5
USER_LED1_GPIO0_C5: J3.130(PWM6/SPI0_MISO_M0/PCIE30X2_WAKEn_M0/GPIO0_C5_d) ; off-sheet USER_LED1_GPIO0_C5
USER_LED2_GPIO1_D0: J3.10(FSPI_CLK/FLASH_ALE/GPIO1_D0_d) ; off-sheet USER_LED2_GPIO1_D0
WIFI_PWREN_L_GPIO0_B7: J3.114(PWM0-M0/CPUAVS/GPIO0_B7_d) ; off-sheet WIFI_PWREN_L_GPIO0_B7
WIFI_REG_ON_H_GPIO3_D5: J3.33(CIF_D7/EBC_SDDO7/SDMMC2_PWREN_M0/I2S1_SDI3_M1/VOP_BT656_D7_M1/GPIO3_D5_d) ; off-sheet WIFI_REG_ON_H_GPIO3_D5
WIFI_WAKE_HOST_H_GPIO3_D4: J3.29(CIF_D6/EBC_SDDO6/SDMMC2_DET_M0/I2S1_SDI2_M1/VOP_BT656_D6_M1/GPIO3_D4_d) ; off-sheet WIFI_WAKE_HOST_H_GPIO3_D4

Not connected (* = marked no-connect by the designer): J3 2(I2S1_SDO1_M0/I2S1_SDI3_M0/PDM_SDI3_M0/PCIE20_CLKREQn_M2/ACODEC_ADC_DATAR/GPIO1_B0_d) 3(SARADC_VIN2_HP_HOOK) 4(I2S1_SDO2_M0/I2S1_SDI2_M0/PDM_SDI2_M0/PCIE20_WAKEn_M2/ACODEC_ADC_SYNC/GPIO1_B1_d) 6(I2S1_SDO3_M0/I2S1_SDI1_M0/PDM_SDI1_M0/PCIE20_PERSTn_M2/GPIO1_B2_d) 7(SARADC_VIN4) 8(I2S1_SCLK_RX_M0/UART4_RX_M0/PDM_CLK1_M0/SPDIF_TX_M0/GPIO1_A4_d) 16(FSPI_D2/FLASH_WPn/GPIO1_C7_d) 57(LCDC_D13/VOP_BT1120_CLK/GMAC1_TXCLK_M0/I2S3_SDI_M0/SDMMC2_CLK_M1/GPIO3_A6_d) 63(LCDC_D10/VOP_BT1120_D2/GMAC1_TXD3_M0/I2S3_SCLK_M0/SDMMC2_D2_M1/GPIO3_A3_d) 72(LCDC_D21/VOP_BT1120_D12/GMAC1_TXD1_M0/I2C3_SDA_M1/PWM11_IR_M0/GPIO3_B6_d) 75(LCDC_D6/VOP_BT656_D6_M0/SPI2_MOSI_M1/PCIE30X2_PERSTn_M1/I2S1_SDI3_M2/GPIO2_D6_d) 77(LCDC_D5/VOP_BT656_D5_M0/SPI2_CS0_M1/PCIE30X2_WAKEn_M1/I2S1_SDI2_M2/GPIO2_D5_d) 79(LCDC_D4/VOP_BT656_D4_M0/SPI2_CS1_M1/PCIE30X2_CLKREQn_M1/I2S1_SDI1_M2/GPIO2_D4_d) 86(MIPI_DSI_TX1_D3P) 88(MIPI_DSI_TX1_D3N) 90(MIPI_DSI_TX1_D2P) 92(MIPI_DSI_TX1_D2N) 94(MIPI_DSI_TX1_CLKP) 96(MIPI_DSI_TX1_CLKN) 98(MIPI_DSI_TX1_D1P) 100(MIPI_DSI_TX1_D1N) 102(MIPI_DSI_TX1_D0P) 104(MIPI_DSI_TX1_D0N) 112(CLK32K_IN/CLK32K_OUT0/PCIE30X2_BUTTONRSTn/GPIO0_B0_u) 120(PWM1_M0/GPUAVS/UART0_RX/GPIO0_C0_d) 122(PWM2_M0/NPUAVS/UART0_TX/MCU_JTAG_TDI/GPIO0_C1_d) 128(PWM5/SPI0_CS1_M0/UART0_RTSn/GPIO0_C4_d) 160(PCIE30_RX1N) 162(PCIE30_RX1P) 164(PCIE30_RX0N) 166(PCIE30_RX0P) 168(PCIE30_TX1N) 170(PCIE30_TX1P) 172(PCIE30_TX0N) 174(PCIE30_TX0P) 176(PCIE30_REFCLKN_IN) 178(PCIE30_REFCLKP_IN) 182(PCIE20_REFCLKP) 184(PCIE20_REFCLKN) 186(PCIE20_RXP/SATA2_RXP/QSGMII_RXP_M1) 188(PCIE20_RXN/SATA2_RXN/QSGMII_RXN_M1) 190(PCIE20_TXP/SATA2_TXP/QSGMII_TXP_M1) 192(PCIE20_TXN/SATA2_TXN/QSGMII_TXN_M1) 197(EDP_TX_AUXN) 199(EDP_TX_AUXP) 201(EDP_TX_D3N) 203(EDP_TX_D3P) 205(EDP_TX_D2N) 207(EDP_TX_D2P) 209(EDP_TX_D1N) 211(EDP_TX_D1P) 213(EDP_TX_D0N) 215(EDP_TX_D0P) 239(BATDIV) 241(SNSP) 243(SNSN) N1 N2

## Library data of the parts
J3 = ATMD097-AED4S-5F_5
